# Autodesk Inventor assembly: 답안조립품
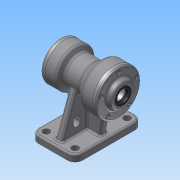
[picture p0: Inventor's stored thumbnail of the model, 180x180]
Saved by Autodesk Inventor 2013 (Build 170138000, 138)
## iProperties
Created: 2015-08
Part Number: 답안조립품
Document SubType Name: Assembly
Designer: Administrator
Author: Administrator
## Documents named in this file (9)
- C:\Users\Administrator\Desktop\450806V1010\답안조립품.iam
- C:\Users\Administrator\Desktop\450806V1010\본체.ipt
- C:\Users\Administrator\Desktop\450806V1010\베어링 6205.ipt
- C:\Users\Administrator\Desktop\450806V1010\베어링 6203.ipt
- C:\Users\Administrator\Desktop\450806V1010\앞커버.ipt
- C:\Users\Administrator\Desktop\450806V1010\오일실 .ipt
- 오일실 .ipt
- C:\Users\Administrator\Desktop\450806V1010\M4x0.5.ipt
- C:\Users\Administrator\Desktop\450806V1010\뒤커버.ipt
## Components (10 placed, 1 different names)
1. M4x0.5:1
2. M4x0.5:2
3. M4x0.5:3
4. M4x0.5:4
5. M4x0.5:5
6. M4x0.5:6
7. M4x0.5:7
8. M4x0.5:8
9. M4x0.5:9
10. M4x0.5:10
